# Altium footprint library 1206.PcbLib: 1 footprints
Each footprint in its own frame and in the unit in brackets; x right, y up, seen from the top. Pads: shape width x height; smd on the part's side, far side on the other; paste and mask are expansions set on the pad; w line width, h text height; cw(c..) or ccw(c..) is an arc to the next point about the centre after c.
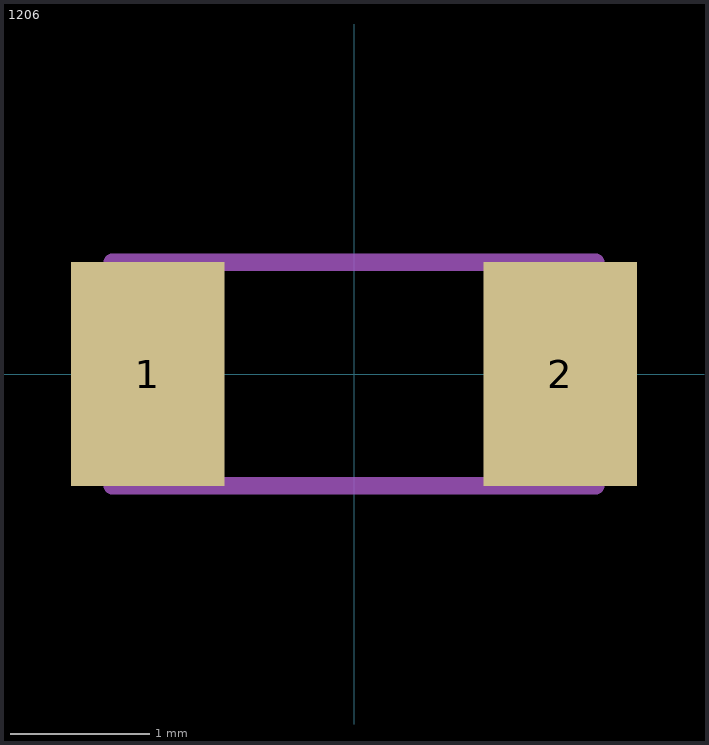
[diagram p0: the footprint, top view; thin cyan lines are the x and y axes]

## 1206 [mm]
pads (2):
  rect 1.1x1.6 smd paste+0 mask+0.102: 1(-1.477,0) 2(1.477,0)
Mechanical 13:
  lines w0.127: -1.73,-0.8 -1.73,0.8 1.73,0.8 1.73,-0.8 -1.73,-0.8
3D body "step_temp.STEP": height 1.7, standoff 0, extent -1.6,-0.8 1.6,0.8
